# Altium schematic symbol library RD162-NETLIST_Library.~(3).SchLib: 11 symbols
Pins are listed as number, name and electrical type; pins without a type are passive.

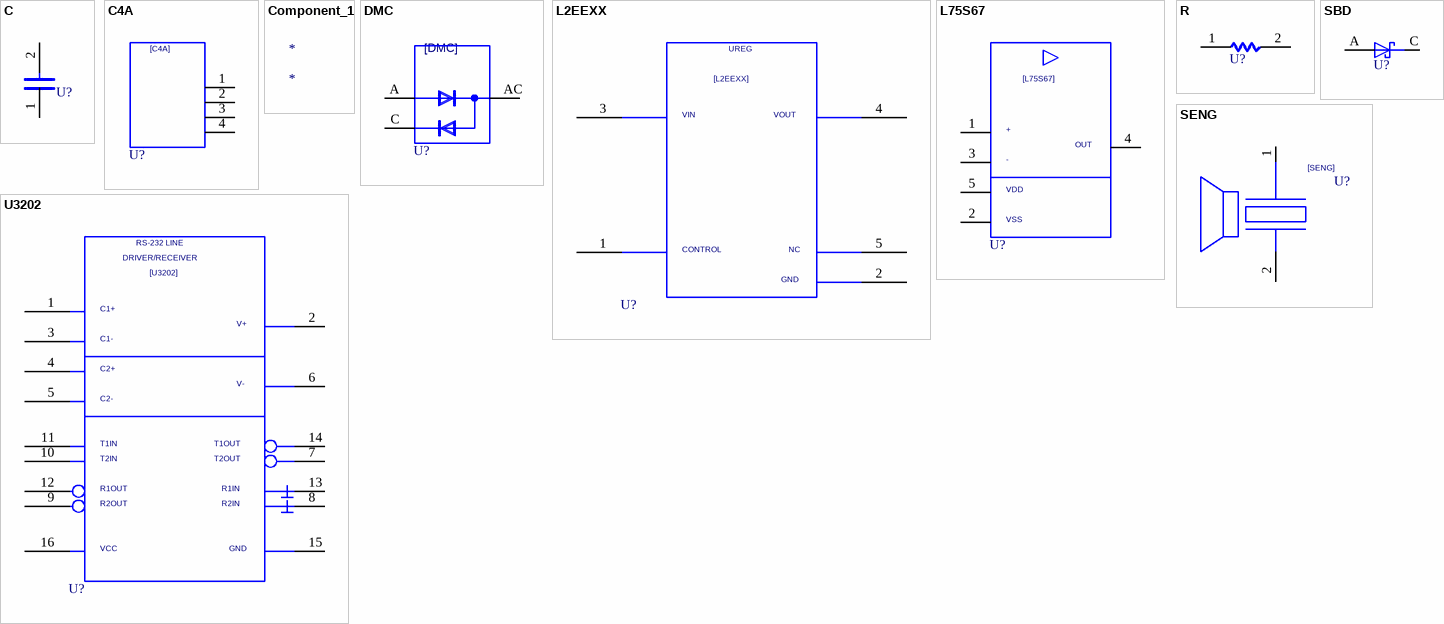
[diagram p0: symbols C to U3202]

## C
designator U?  (value not drawn)
OriginalSymbolOrigin: (2540,7620); Altium-Right: 20; Altium-Bottom: 10
pins: 1, 2

## C4A
designator U?  (value not drawn)
SAVEAREA0: -8845,-265,28754,23475; SAVECOUNT: 22; TIME: 13:28:28; UPDATEUSER: tomizawa-y; UPDATETIME: 15:03:27; OriginalSymbolOrigin: (2540,20320); Altium-Right: 50; Altium-Bottom: 70
pins: 1, 2, 3, 4

## Component_1
designator *

## DMC
designator U?  (value not drawn)
OriginalSymbolOrigin: (5080,20320); Altium-Right: 50; Altium-Bottom: 70
pins: A, AC, C

## L2EEXX
designator U?  (value not drawn)
TIME: 08:44:39; UPDATEUSER: 19990028; UPDATETIME: 08:53:29; SAVECOUNT: 98; SAVEAREA0: -21552,-545,77535,48780; OriginalSymbolOrigin: (7620,45720); Altium-Right: 160; Altium-Bottom: 170
pins: 1, 2, 3, 4, 5

## L75S67
designator U?  (value not drawn)
TIME: 16:27:13; UPDATEUSER: w90028dm; UPDATETIME: 15:17:13; SAVECOUNT: 13; SAVEAREA0: -43421,-10273,73920,48138; OriginalSymbolOrigin: (5080,35560); Altium-Right: 80; Altium-Bottom: 130
pins: 1, 2, 3, 4, 5

## R
designator U?  (value not drawn)
OriginalSymbolOrigin: (5080,5080); Altium-Right: 20
pins: 1, 2

## SBD
designator U?  (value not drawn)
SAVEAREA0: -4630,-153,17114,13055; TIME: 14:49:55; UPDATEUSER: fukuda-y; UPDATETIME: 08:16:22; SAVECOUNT: 9; OriginalSymbolOrigin: (5080,5080); Altium-Right: 20
pins: A, C

## SENG
designator U?  (value not drawn)
SAVEAREA0: -37507,-14886,68094,37681; SAVECOUNT: 6; TIME: 16:49:52; UPDATEUSER: w90028dm; UPDATETIME: 08:15:42; OriginalSymbolOrigin: (2540,20320); Altium-Right: 70; Altium-Bottom: 60
pins: 1, 2

## U3202
designator U?  (value not drawn)
SAVECOUNT: 55; SAVEAREA0: -39703,-717,90678,64185; TIME: 16:13:33; UPDATEUSER: w90028dm; UPDATETIME: 08:35:39; OriginalSymbolOrigin: (7620,60960); Altium-Right: 150; Altium-Bottom: 230
pins: 1, 2, 3, 4, 5, 6, 7, 8, 9, 10, 11, 12, 13, 14, 15, 16

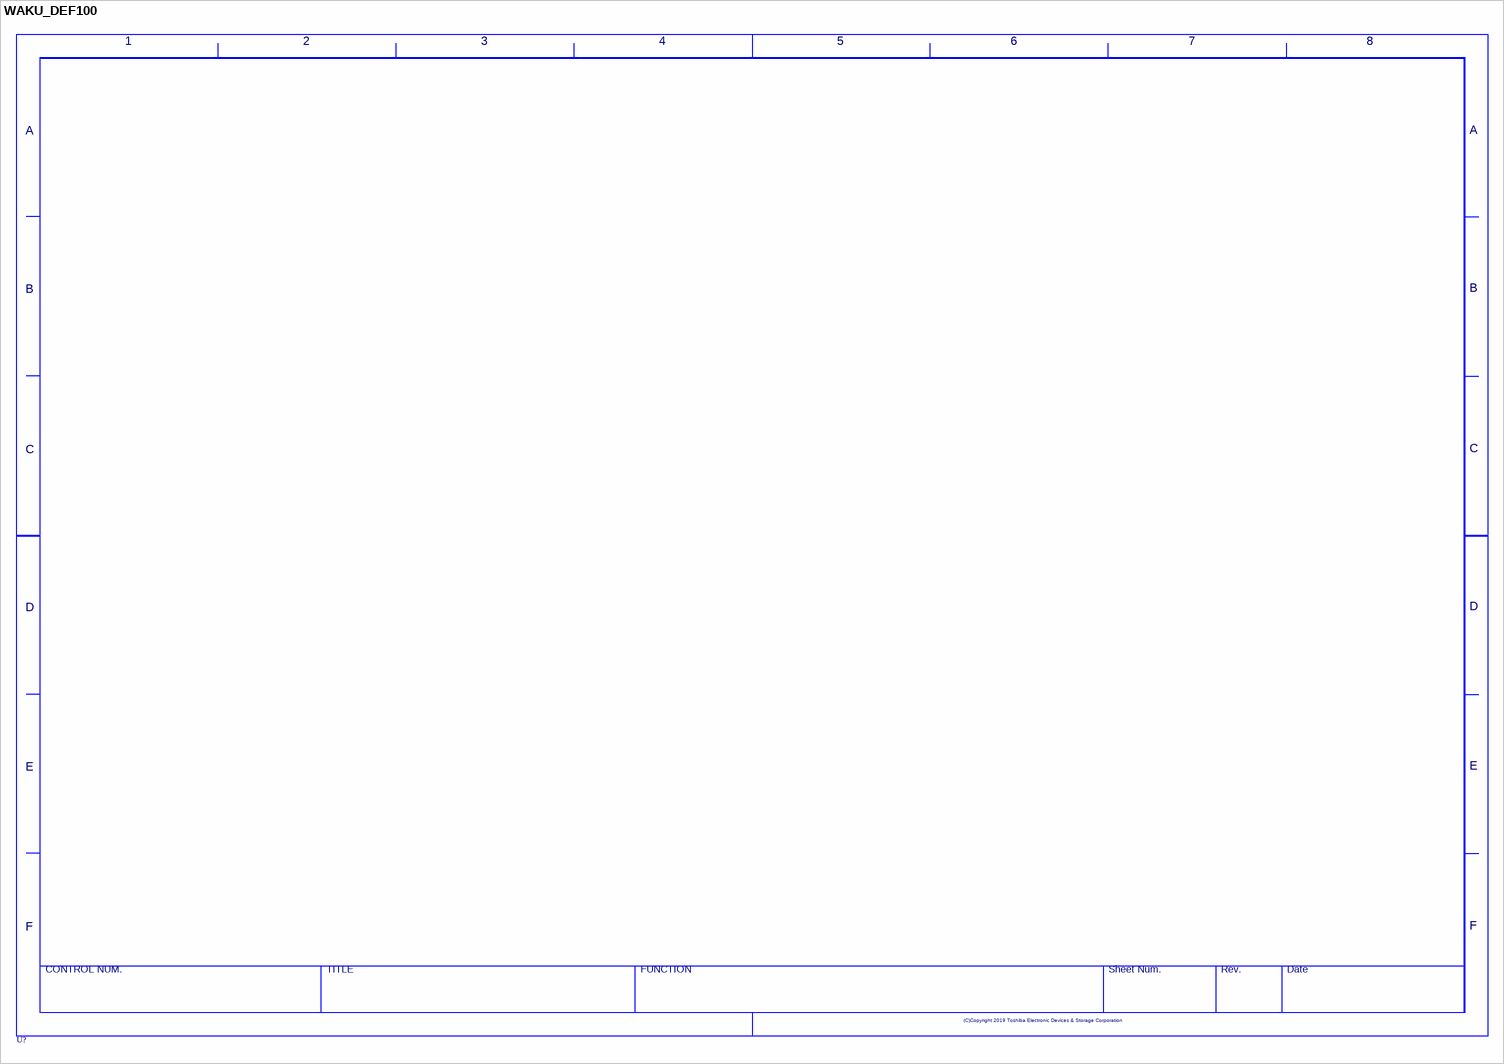
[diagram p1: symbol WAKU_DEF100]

## WAKU_DEF100
designator U?  (value not drawn)
PLOTTIME: HH:MM; SAVEAREA0: 198008,-65938,436964,90161; TIME: 14:30:25; UPDATEUSER: d5009410; UPDATETIME: 15:37:05; SAVECOUNT: 4; OriginalSymbolOrigin: (10160,284480); Altium-Right: 1570; Altium-Bottom: 1070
